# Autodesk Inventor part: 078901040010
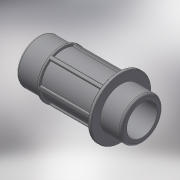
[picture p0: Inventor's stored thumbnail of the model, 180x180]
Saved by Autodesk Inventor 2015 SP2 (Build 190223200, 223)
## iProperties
Created: 2018-02
Part Number: 078901040010
Material: Generic
Description: PLASSON THREADED MALE ADAPTOR 40-1"
Document SubType Name: Modeling
Designer: KIM
Density: 1 g/cm^3
Appearance: Default
Author: KIM
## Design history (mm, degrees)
derived "078901.ipt"
feature "Solid1::078901.ipt"
tag "TaggingFeature1"
body "Solid1"
other parameters: "d4" = 1.66245, "d14" = 2.65992, "d15" = 1.32996, "d17" = 0, "d20" = 360 deg, "d41" = 33.249, "d45" = 36.5739, "d46" = 23.2743, "d47" = 2, "d85" = 0.33249, "d103" = 23, "d104" = 58, "d105" = 0.33249, "R_" = 33.249, "E_" = 58
